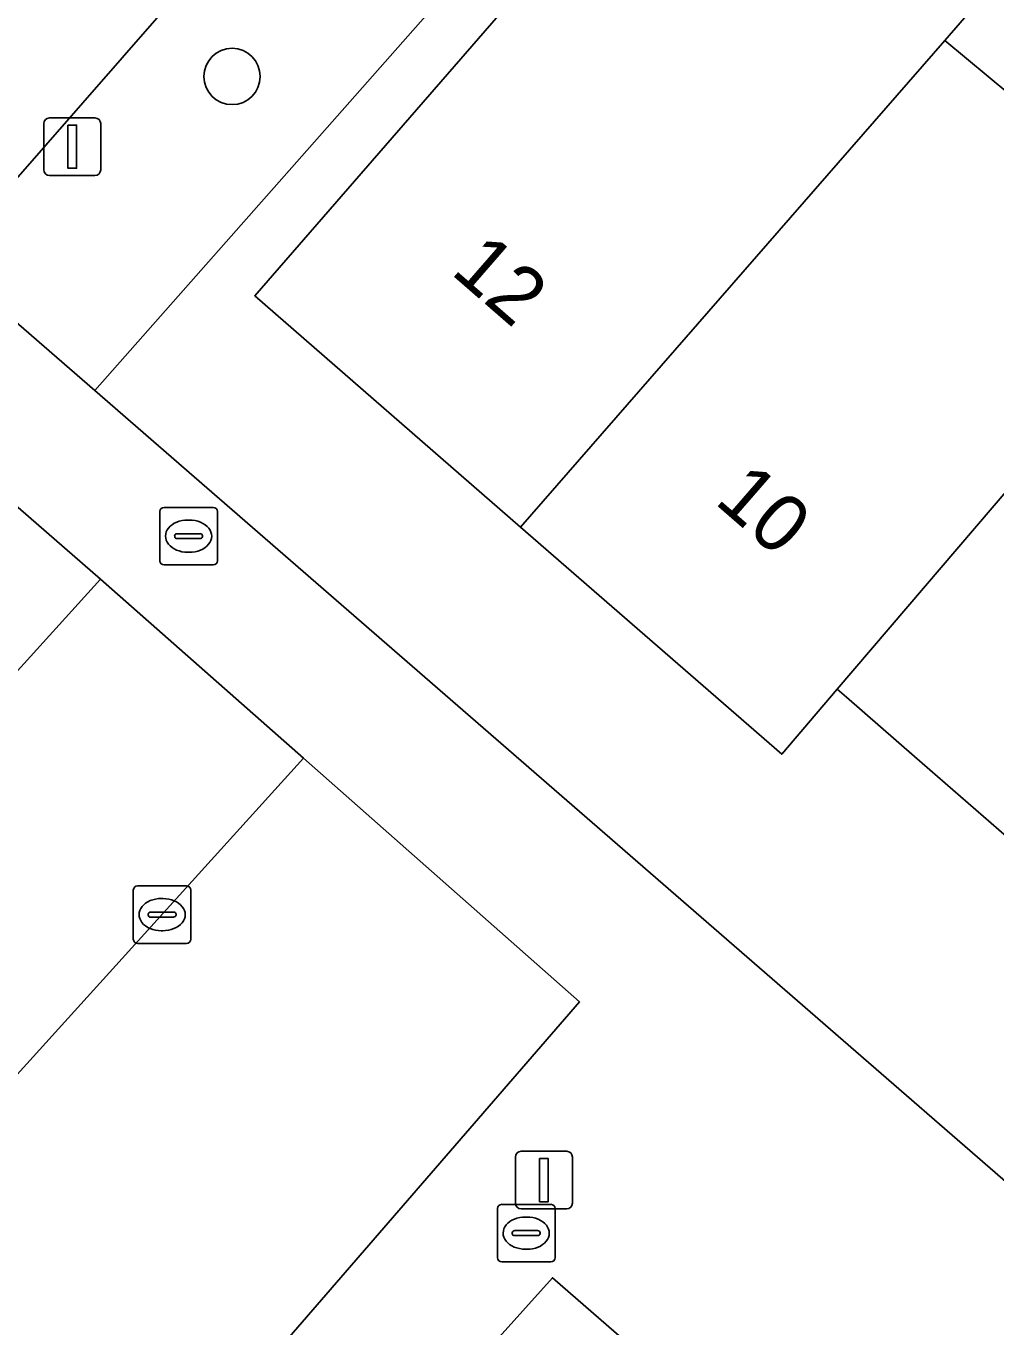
# Model space of a CAD drawing. Extents: x 158472 to 159562, y 388525 to 389606.
# Drawn here: x 158933.03 to 158949.88, y 388825.82 to 388848.41 of the extents above; entities that cross this region are included whole.
import ezdxf

# ---------------------------------------------------------------- set-up
doc = ezdxf.new("R2010")
doc.units = 0
for name, color, linetype in [('IMGEO_Berm_groen', 7, 'Continuous'), ('IMGEO_Boom', 7, 'Continuous'), ('IMGEO_Brandkraan', 7, 'Continuous'), ('IMGEO_Erf', 7, 'Continuous'), ('IMGEO_Fietspad_gesloten', 7, 'Continuous'), ('IMGEO_Groenvoorziening', 7, 'Continuous'), ('IMGEO_Kolk', 7, 'Continuous'), ('IMGEO_Lichtmast', 7, 'Continuous'), ('IMGEO_Pand', 7, 'Continuous'), ('IMGEO_Pand_nummerreeks', 7, 'Continuous'), ('IMGEO_Parkeervlak_open', 7, 'Continuous'), ('IMGEO_Rijbaan_lokaal_open', 7, 'Continuous'), ('IMGEO_Voetpad_open', 7, 'Continuous')]:
    doc.layers.add(name, color=color, linetype=linetype)

msp = doc.modelspace()

# ---------------------------------------------------------------- linework, layer by layer
at = {"layer": 'IMGEO_Berm_groen'}
for points in [[(158954.488, 388865.021), (158951.767, 388867.379), (158941.937, 388856.138), (158932.045, 388844.827)], [(158932.107, 388843.92), (158934.223, 388842.084), (158954.488, 388865.021)]]:
    msp.add_lwpolyline(points, dxfattribs=at)
at = {"layer": 'IMGEO_Boom'}
msp.add_circle((158936.61, 388847.539), 0.489, dxfattribs=at)
at = {"layer": 'IMGEO_Brandkraan'}
for p, q in [((158935.354, 388839.13), (158935.354, 388839.982)), ((158935.429, 388840.056), (158936.281, 388840.056)), ((158936.355, 388839.982), (158936.355, 388839.13)), ((158935.842, 388839.836), (158935.867, 388839.836)), ((158935.613, 388839.55), (158935.613, 388839.562)), ((158936.051, 388839.513), (158935.653, 388839.513)), ((158935.656, 388839.599), (158936.054, 388839.599)), ((158936.097, 388839.562), (158936.097, 388839.55)), ((158935.865, 388839.276), (158935.84, 388839.276)), ((158936.281, 388839.056), (158935.429, 388839.056))]:
    msp.add_line(p, q, dxfattribs=at)
for points in [[(158935.354, 388839.13), (158935.354, 388839.982)], [(158935.429, 388840.056), (158936.281, 388840.056)], [(158936.355, 388839.982), (158936.355, 388839.13)], [(158936.281, 388839.056), (158935.429, 388839.056)]]:
    msp.add_lwpolyline(points, dxfattribs=at)
for centre, radius, start, end in [((158935.431, 388839.98), 0.0765, 91.552, 178.448), ((158935.431, 388839.98), 0.0765, 91.552, 178.448), ((158936.279, 388839.98), 0.0765, 1.552, 88.448), ((158936.279, 388839.98), 0.0765, 1.552, 88.448), ((158935.653, 388839.559), 0.0403, 85.8775, 175.7526), ((158935.65, 388839.549), 0.0366, 178.938, 274.7102), ((158936.054, 388839.556), 0.043, 264.8664, 352.4533), ((158936.058, 388839.561), 0.0386, 1.7309, 96.639), ((158935.431, 388839.132), 0.0765, 181.552, 268.448), ((158935.431, 388839.132), 0.0765, 181.552, 268.448), ((158936.279, 388839.132), 0.0765, 271.552, 358.448), ((158936.279, 388839.132), 0.0765, 271.552, 358.448)]:
    msp.add_arc(centre, radius, start, end, dxfattribs=at)
for centre, major_axis, ratio, start_param, end_param in [((158935.841, 388839.556), (-0.387, 0.002), 0.722429, 4.712389, 7.853982), ((158935.866, 388839.556), (-0.39, 0.002), 0.717154, 1.570796, 4.712389)]:
    msp.add_ellipse(centre, major_axis=major_axis, ratio=ratio, start_param=start_param, end_param=end_param, dxfattribs=at)
at = {"layer": 'IMGEO_Erf'}
for points in [[(158977.456, 388853.29), (158973.547, 388848.892), (158968.923, 388852.867), (158967.178, 388850.853), (158965.638, 388852.177), (158967.382, 388854.192), (158964.404, 388856.752), (158959.822, 388860.691), (158960.987, 388862.036), (158956.052, 388866.312), (158955.835, 388866.062), (158955.593, 388866.271), (158954.488, 388865.021), (158934.223, 388842.084), (158935.951, 388840.584), (158962.949, 388817.149), (158977.95, 388834.432)], [(158951.665, 388832.95), (158948.465, 388835.731), (158947.284, 388836.758), (158947.124, 388836.897), (158946.16, 388835.769), (158941.622, 388839.714), (158937.003, 388843.73), (158944.893, 388852.805)], [(158949.529, 388848.779), (158948.993, 388848.164), (158951.254, 388846.286)]]:
    msp.add_lwpolyline(points, dxfattribs=at)
at = {"layer": 'IMGEO_Fietspad_gesloten'}
msp.add_lwpolyline([(158939.547, 388858.13), (158926.586, 388843.327), (158908.631, 388822.912), (158891.98, 388803.837), (158886.534, 388797.524), (158886.262, 388797.803), (158884.323, 388795.61), (158883.327, 388794.483), (158872.522, 388782.263), (158876.002, 388779.209), (158877.157, 388780.522), (158889.917, 388795.054), (158889.244, 388795.75), (158891.577, 388798.482), (158892.838, 388800.078), (158918.64, 388829.712), (158922.701, 388834.313), (158925.978, 388838.056), (158929.322, 388841.85), (158932.045, 388844.827), (158941.937, 388856.138)], dxfattribs=at)
at = {"layer": 'IMGEO_Groenvoorziening'}
msp.add_lwpolyline([(158932.722, 388837.039), (158934.325, 388838.808), (158930.748, 388841.919)], dxfattribs=at)
at = {"layer": 'IMGEO_Kolk'}
for p, q in [((158934.894, 388832.558), (158934.894, 388833.41)), ((158934.969, 388833.484), (158935.821, 388833.484)), ((158935.895, 388833.41), (158935.895, 388832.558)), ((158935.382, 388833.264), (158935.407, 388833.264)), ((158935.153, 388832.978), (158935.153, 388832.99)), ((158935.591, 388832.941), (158935.193, 388832.941)), ((158935.196, 388833.027), (158935.594, 388833.027)), ((158935.637, 388832.99), (158935.637, 388832.978)), ((158935.405, 388832.704), (158935.38, 388832.704)), ((158935.821, 388832.484), (158934.969, 388832.484)), ((158941.295, 388827.953), (158942.147, 388827.953)), ((158941.22, 388827.027), (158941.22, 388827.879)), ((158941.708, 388827.733), (158941.733, 388827.733)), ((158942.221, 388827.879), (158942.221, 388827.027)), ((158941.522, 388827.496), (158941.92, 388827.496)), ((158941.479, 388827.447), (158941.479, 388827.459)), ((158941.917, 388827.41), (158941.519, 388827.41)), ((158941.963, 388827.459), (158941.963, 388827.447)), ((158941.731, 388827.173), (158941.706, 388827.173)), ((158942.147, 388826.953), (158941.295, 388826.953))]:
    msp.add_line(p, q, dxfattribs=at)
for points in [[(158934.894, 388832.558), (158934.894, 388833.41)], [(158934.969, 388833.484), (158935.821, 388833.484)], [(158935.895, 388833.41), (158935.895, 388832.558)], [(158935.821, 388832.484), (158934.969, 388832.484)], [(158941.295, 388827.953), (158942.147, 388827.953)], [(158941.22, 388827.027), (158941.22, 388827.879)], [(158942.221, 388827.879), (158942.221, 388827.027)], [(158942.147, 388826.953), (158941.295, 388826.953)]]:
    msp.add_lwpolyline(points, dxfattribs=at)
for centre, radius, start, end in [((158934.971, 388833.408), 0.0765, 91.552, 178.448), ((158934.971, 388833.408), 0.0765, 91.552, 178.448), ((158935.819, 388833.408), 0.0765, 1.552, 88.448), ((158935.819, 388833.408), 0.0765, 1.552, 88.448), ((158935.193, 388832.987), 0.0403, 85.8775, 175.7526), ((158935.19, 388832.977), 0.0366, 178.938, 274.7102), ((158935.594, 388832.984), 0.043, 264.8664, 352.4533), ((158935.598, 388832.989), 0.0386, 1.7309, 96.639), ((158934.971, 388832.56), 0.0765, 181.552, 268.448), ((158934.971, 388832.56), 0.0765, 181.552, 268.448), ((158935.819, 388832.56), 0.0765, 271.552, 358.448), ((158935.819, 388832.56), 0.0765, 271.552, 358.448), ((158941.297, 388827.877), 0.0765, 91.552, 178.448), ((158941.297, 388827.877), 0.0765, 91.552, 178.448), ((158942.145, 388827.877), 0.0765, 1.552, 88.448), ((158942.145, 388827.877), 0.0765, 1.552, 88.448), ((158941.519, 388827.456), 0.0403, 85.8775, 175.7526), ((158941.924, 388827.458), 0.0386, 1.7309, 96.639), ((158941.516, 388827.446), 0.0366, 178.938, 274.7102), ((158941.92, 388827.453), 0.043, 264.8664, 352.4533), ((158941.297, 388827.029), 0.0765, 181.552, 268.448), ((158941.297, 388827.029), 0.0765, 181.552, 268.448), ((158942.145, 388827.029), 0.0765, 271.552, 358.448), ((158942.145, 388827.029), 0.0765, 271.552, 358.448)]:
    msp.add_arc(centre, radius, start, end, dxfattribs=at)
for centre, major_axis, ratio, start_param, end_param in [((158935.381, 388832.984), (-0.387, 0.002), 0.722429, 4.712389, 7.853982), ((158935.406, 388832.984), (-0.39, 0.002), 0.717154, 1.570796, 4.712389), ((158941.707, 388827.453), (-0.387, 0.002), 0.722429, 4.712389, 7.853982), ((158941.732, 388827.453), (-0.39, 0.002), 0.717154, 1.570796, 4.712389)]:
    msp.add_ellipse(centre, major_axis=major_axis, ratio=ratio, start_param=start_param, end_param=end_param, dxfattribs=at)
at = {"layer": 'IMGEO_Lichtmast'}
for p, q in [((158933.338, 388845.919), (158933.338, 388846.719)), ((158933.338, 388846.719), (158933.338, 388845.919)), ((158933.438, 388846.819), (158934.228, 388846.819)), ((158934.228, 388846.819), (158933.438, 388846.819)), ((158934.328, 388846.719), (158934.328, 388845.919)), ((158934.328, 388845.919), (158934.328, 388846.719)), ((158934.228, 388845.819), (158933.438, 388845.819)), ((158933.438, 388845.819), (158934.228, 388845.819)), ((158941.634, 388828.874), (158942.424, 388828.874)), ((158942.424, 388828.874), (158941.634, 388828.874)), ((158941.534, 388827.974), (158941.534, 388828.774)), ((158941.534, 388828.774), (158941.534, 388827.974)), ((158942.524, 388828.774), (158942.524, 388827.974)), ((158942.524, 388827.974), (158942.524, 388828.774)), ((158942.424, 388827.874), (158941.634, 388827.874)), ((158941.634, 388827.874), (158942.424, 388827.874))]:
    msp.add_line(p, q, dxfattribs=at)
for points in [[(158933.758, 388846.694), (158933.908, 388846.694), (158933.908, 388845.944), (158933.758, 388845.944), (158933.758, 388846.694)], [(158941.954, 388828.749), (158942.104, 388828.749), (158942.104, 388827.999), (158941.954, 388827.999), (158941.954, 388828.749)]]:
    msp.add_lwpolyline(points, dxfattribs=at)
for centre, start, end in [((158933.438, 388846.719), 90, 180), ((158933.438, 388846.719), 90, 180), ((158934.228, 388846.719), 0, 90), ((158934.228, 388846.719), 360, 90), ((158933.438, 388845.919), 180, 270), ((158933.438, 388845.919), 180, 270), ((158934.228, 388845.919), 270, 0), ((158934.228, 388845.919), 270, 0), ((158941.634, 388828.774), 90, 180), ((158941.634, 388828.774), 90, 180), ((158942.424, 388828.774), 0, 90), ((158942.424, 388828.774), 360, 90), ((158941.634, 388827.974), 180, 270), ((158941.634, 388827.974), 180, 270), ((158942.424, 388827.974), 270, 0), ((158942.424, 388827.974), 270, 0)]:
    msp.add_arc(centre, 0.1, start, end, dxfattribs=at)
at = {"layer": 'IMGEO_Pand'}
for points in [[(158941.622, 388839.714), (158948.993, 388848.164), (158949.529, 388848.779), (158949.324, 388848.955), (158949.185, 388848.795), (158946.025, 388851.524), (158944.985, 388852.422), (158945.135, 388852.596), (158944.893, 388852.805), (158937.003, 388843.73)], [(158953.051, 388843.819), (158950.775, 388845.709), (158951.254, 388846.286), (158948.993, 388848.164), (158941.622, 388839.714), (158946.16, 388835.769), (158947.124, 388836.897), (158952.545, 388843.238)], [(158953.051, 388843.819), (158952.545, 388843.238), (158947.124, 388836.897), (158947.284, 388836.758), (158948.465, 388835.731), (158951.665, 388832.95), (158957.128, 388839.255), (158959.26, 388841.376), (158958.287, 388842.222), (158954.514, 388845.501), (158954.223, 388845.166)]]:
    msp.add_lwpolyline(points, close=True, dxfattribs=at)
at = {"layer": 'IMGEO_Parkeervlak_open'}
for points in [[(158937.853, 388835.702), (158934.325, 388838.808), (158932.722, 388837.039), (158928.005, 388831.661), (158928.578, 388831.153), (158931.435, 388828.62)], [(158939.082, 388823.238), (158955.341, 388809.01), (158958.574, 388812.427), (158942.175, 388826.678)]]:
    msp.add_lwpolyline(points, close=True, dxfattribs=at)
at = {"layer": 'IMGEO_Rijbaan_lokaal_open'}
for points in [[(158942.646, 388831.471), (158937.853, 388835.702), (158931.435, 388828.62), (158928.578, 388831.153)], [(158927.054, 388829.223), (158926.892, 388829.365), (158924.182, 388826.315), (158927.08, 388823.739), (158928.05, 388824.862), (158959.175, 388797.838), (158965.788, 388805.265), (158969.246, 388809.149), (158962.92, 388814.631), (158959.478, 388810.733), (158956.854, 388807.76), (158955.341, 388809.01), (158939.082, 388823.238), (158937.005, 388824.955), (158942.646, 388831.471)]]:
    msp.add_lwpolyline(points, dxfattribs=at)
at = {"layer": 'IMGEO_Voetpad_open'}
for points in [[(158964.083, 388816.165), (158962.949, 388817.149), (158935.951, 388840.584), (158934.223, 388842.084), (158932.107, 388843.92)], [(158930.748, 388841.919), (158934.325, 388838.808), (158937.853, 388835.702), (158942.646, 388831.471), (158937.005, 388824.955), (158939.082, 388823.238), (158942.175, 388826.678), (158958.574, 388812.427), (158955.341, 388809.01), (158956.854, 388807.76), (158959.478, 388810.733), (158962.92, 388814.631), (158969.246, 388809.149), (158965.788, 388805.265), (158969.296, 388802.14), (158970.588, 388801.233), (158972.066, 388799.994), (158973.085, 388801.192), (158975.512, 388804.045), (158976.586, 388805.308), (158975.565, 388806.198), (158975.043, 388806.651), (158969.67, 388811.315), (158964.083, 388816.165)]]:
    msp.add_lwpolyline(points, dxfattribs=at)

# ---------------------------------------------------------------- texts
at = {"layer": 'IMGEO_Pand_nummerreeks'}
for s, rotation, p in [('12', 318.9966, (158940.389, 388844.126)), ('10', 318.9991, (158944.971, 388840.141))]:
    msp.add_text(s, height=1, rotation=rotation, dxfattribs=at).set_placement(p)

doc.saveas('drawing.dxf')
